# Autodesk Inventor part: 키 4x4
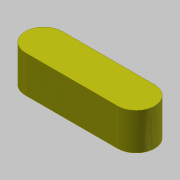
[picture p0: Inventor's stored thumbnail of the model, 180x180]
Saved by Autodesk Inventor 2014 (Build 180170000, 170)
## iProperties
Created: 2018-09
Part Number: 키 4x4
Document SubType Name: Modeling
Density: 7.86 g/cm^3
Material: 강철, 연강
Appearance: 노란색
Mass: 1.65269 g
Surface Area: 2.35398 cm^2
Volume: 0.210265 cm^3
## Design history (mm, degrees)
sketch "스케치1"
  geometry: L1 (-5, -2)-(5, -2); L2 (5, 2)-(-5, 2); A1 r 2 centre (5, 0) between (5, -2) and (5, 2); A2 r 2 centre (-5, 0) between (-5, 2) and (-5, -2); 2 further points
  constraints: 4 end point, 4 point on circle, 4 tangent, 2 centre point, 1 horizontal, 1 horizontal alignment, 1 midpoint, 1 parallel, 1 vertical alignment
  dimensions: "d0" = 4 distance between parallel lines of L1 L2; "d1" = 14 dimension on A1 A2
extrude "돌출1" new body sketch "스케치1" stored distance "d2" = 4; taper "d3" = 0 deg
node "솔리드1"
